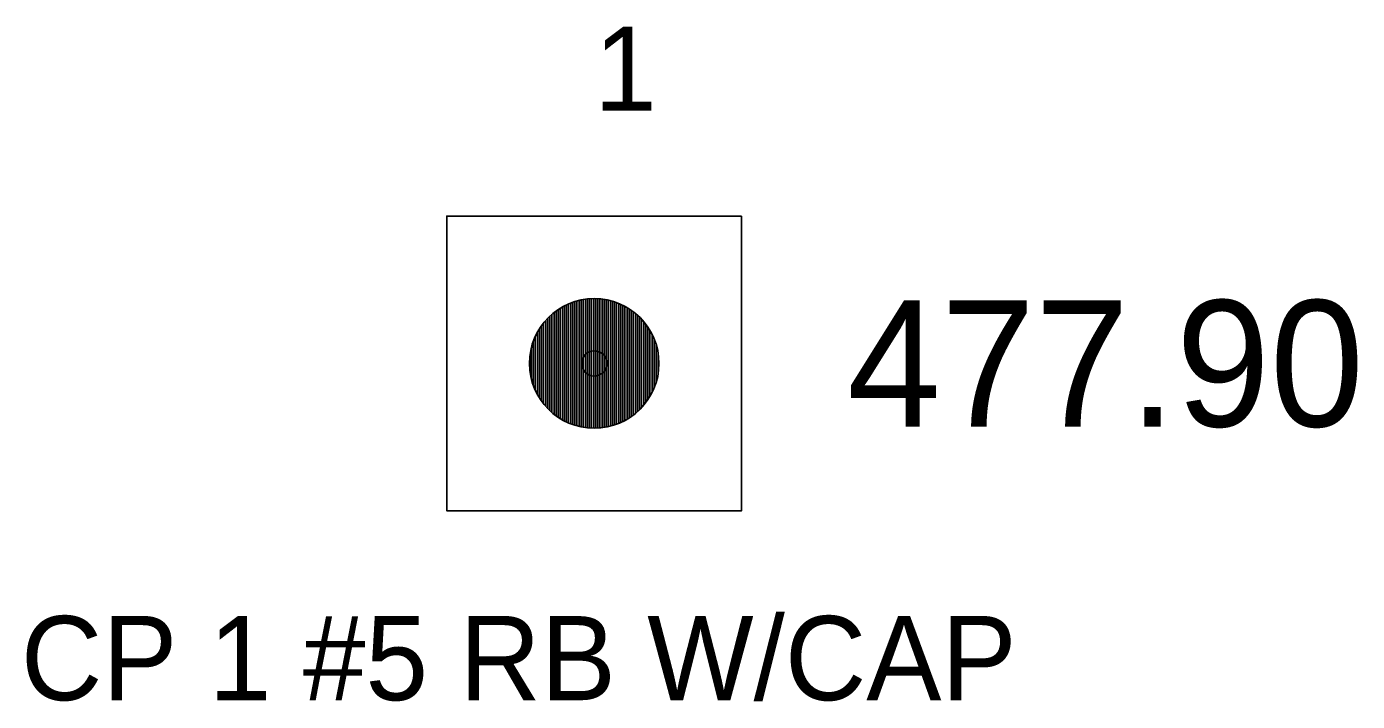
# Model space of a CAD drawing. Extents: x 1762456 to 1764480, y 822234 to 826541.
# Drawn here: x 1764303.71 to 1764319.5, y 825716.18 to 825724.2 of the extents above; entities that cross this region are included whole.
import ezdxf

# ---------------------------------------------------------------- set-up
doc = ezdxf.new("R2010")
doc.units = 0
for name, color, linetype in [('RD_HC_Survey', 7, 'Continuous'), ('RD_HC_Survey_ELEV', 7, 'Continuous'), ('RD_HC_Survey_txCode', 7, 'Continuous'), ('RD_SMD_Locator', 7, 'Continuous')]:
    doc.layers.add(name, color=color, linetype=linetype)

msp = doc.modelspace()

# ---------------------------------------------------------------- linework, layer by layer
at = {"layer": 'RD_HC_Survey'}
for p, q in [((1764310.164, 825719.482), (1764310.164, 825720.916)), ((1764310.189, 825719.472), (1764310.189, 825720.926)), ((1764310.213, 825719.464), (1764310.213, 825720.934)), ((1764310.238, 825719.457), (1764310.238, 825720.941)), ((1764310.263, 825719.451), (1764310.263, 825720.947)), ((1764310.288, 825719.445), (1764310.288, 825720.953)), ((1764310.312, 825719.441), (1764310.312, 825720.957)), ((1764310.337, 825719.437), (1764310.337, 825720.961)), ((1764310.362, 825719.434), (1764310.362, 825720.964)), ((1764310.387, 825719.432), (1764310.387, 825720.966)), ((1764310.411, 825719.43), (1764310.411, 825720.968)), ((1764310.436, 825719.43), (1764310.436, 825720.968)), ((1764310.461, 825719.43), (1764310.461, 825720.968)), ((1764310.486, 825719.431), (1764310.486, 825720.967)), ((1764310.51, 825719.433), (1764310.51, 825720.965)), ((1764310.535, 825719.435), (1764310.535, 825720.963)), ((1764310.56, 825719.439), (1764310.56, 825720.959)), ((1764310.585, 825719.443), (1764310.585, 825720.955)), ((1764310.609, 825719.448), (1764310.609, 825720.95)), ((1764310.634, 825719.454), (1764310.634, 825720.944)), ((1764310.659, 825719.461), (1764310.659, 825720.937)), ((1764310.684, 825719.468), (1764310.684, 825720.93)), ((1764310.708, 825719.477), (1764310.708, 825720.921)), ((1764309.916, 825719.637), (1764309.916, 825720.761)), ((1764309.941, 825719.615), (1764309.941, 825720.783)), ((1764309.966, 825719.595), (1764309.966, 825720.803)), ((1764309.991, 825719.576), (1764309.991, 825720.822)), ((1764310.015, 825719.559), (1764310.015, 825720.839)), ((1764310.04, 825719.543), (1764310.04, 825720.855)), ((1764310.065, 825719.528), (1764310.065, 825720.87)), ((1764310.09, 825719.515), (1764310.09, 825720.883)), ((1764310.114, 825719.503), (1764310.114, 825720.895)), ((1764310.139, 825719.492), (1764310.139, 825720.906)), ((1764310.733, 825719.487), (1764310.733, 825720.911)), ((1764310.758, 825719.497), (1764310.758, 825720.901)), ((1764310.783, 825719.509), (1764310.783, 825720.889)), ((1764310.807, 825719.522), (1764310.807, 825720.876)), ((1764310.832, 825719.536), (1764310.832, 825720.862)), ((1764310.857, 825719.551), (1764310.857, 825720.847)), ((1764310.882, 825719.567), (1764310.882, 825720.831)), ((1764310.906, 825719.585), (1764310.906, 825720.813)), ((1764310.931, 825719.605), (1764310.931, 825720.793)), ((1764310.956, 825719.626), (1764310.956, 825720.772)), ((1764309.793, 825719.786), (1764309.793, 825720.612)), ((1764309.817, 825719.75), (1764309.817, 825720.648)), ((1764309.842, 825719.717), (1764309.842, 825720.681)), ((1764309.867, 825719.688), (1764309.867, 825720.71)), ((1764309.892, 825719.661), (1764309.892, 825720.737)), ((1764310.981, 825719.649), (1764310.981, 825720.749)), ((1764311.005, 825719.675), (1764311.005, 825720.723)), ((1764311.03, 825719.703), (1764311.03, 825720.695)), ((1764311.055, 825719.734), (1764311.055, 825720.664)), ((1764311.08, 825719.768), (1764311.08, 825720.63)), ((1764309.718, 825719.937), (1764309.718, 825720.461)), ((1764309.743, 825719.877), (1764309.743, 825720.521)), ((1764309.768, 825719.828), (1764309.768, 825720.57)), ((1764311.104, 825719.807), (1764311.104, 825720.591)), ((1764311.129, 825719.853), (1764311.129, 825720.545)), ((1764311.154, 825719.907), (1764311.154, 825720.491)), ((1764309.694, 825720.02), (1764309.694, 825720.378)), ((1764311.179, 825719.976), (1764311.179, 825720.422)), ((1764311.203, 825720.087), (1764311.203, 825720.311))]:
    msp.add_line(p, q, dxfattribs=at)
msp.add_lwpolyline([(1764312.192, 825721.949), (1764308.692, 825721.949), (1764308.692, 825718.449), (1764312.192, 825718.449)], close=True, dxfattribs=at)
msp.add_circle((1764310.442, 825720.199), 0.769, dxfattribs=at)
at = {"layer": 'RD_SMD_Locator'}
msp.add_circle((1764310.442, 825720.199), 0.15, dxfattribs=at)

# ---------------------------------------------------------------- texts
at = {"layer": 'RD_HC_Survey_ELEV'}
msp.add_text('477.90', height=1.5, dxfattribs=at).set_placement((1764313.442, 825719.449))
at = {"layer": 'RD_HC_Survey_txCode'}
for s, p in [('1', (1764310.442, 825723.199)), ('CP 1 #5 RB W/CAP', (1764303.639, 825716.199))]:
    msp.add_text(s, height=1, dxfattribs=at).set_placement(p)

doc.saveas('drawing.dxf')
